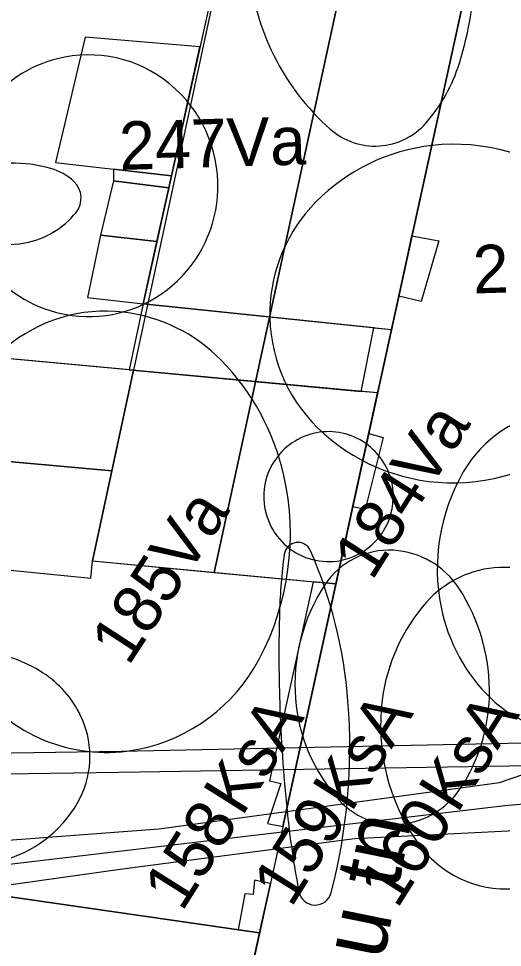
# Model space of a CAD drawing. Extents: x 738423 to 738903, y 6589762 to 6590172.
# Drawn here: x 738682.86 to 738697.88, y 6589875.99 to 6589904.84 of the extents above; entities that cross this region are included whole.
import ezdxf

# ---------------------------------------------------------------- set-up
doc = ezdxf.new("R2010")
doc.units = 0
for name, color, linetype in [('_1927_hoonestus', 7, 'Continuous'), ('_1927_katuse_kalded', 7, 'Continuous'), ('_1927_koordin_punktid_nr', 7, 'Continuous'), ('_1927_krundi_piir', 7, 'Continuous'), ('a_dendro_II_Vkl_puu', 7, 'Continuous'), ('a_dendro_III_vk_puu', 7, 'Continuous'), ('a_dendro_puu_nr', 7, 'Continuous'), ('a_dendro_V_vk_puu', 7, 'Continuous'), ('Default', 7, 'Continuous'), ('v_dp_jalak_liikumine', 7, 'Continuous'), ('v_olol_kivimuur', 7, 'Continuous'), ('v_olol_transp_jjt_jalg', 7, 'Continuous')]:
    doc.layers.add(name, color=color, linetype=linetype)

# ---------------------------------------------------------------- blocks, each defined once
blk = doc.blocks.new('_U607')
at = {"layer": 'Default'}
for centre, radius, start, end in [((-0.0026566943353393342, 0.002417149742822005), 0.005933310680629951, 70.41382597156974, 140.13835243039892), ((-0.0029635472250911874, 0.0015547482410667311), 0.006848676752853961, 31.851207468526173, 70.41382597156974), ((-0.0009113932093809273, 0.0009598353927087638), 0.008207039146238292, 140.13835243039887, 198.29664430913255), ((-0.004453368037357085, 0.0006291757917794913), 0.008602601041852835, 357.58074074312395, 31.8512074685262), ((-0.004046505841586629, 0.0006119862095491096), 0.008195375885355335, 329.5158395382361, 357.58074074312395), ((-0.0014782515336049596, 0.0007724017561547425), 0.007609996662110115, 198.29664430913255, 244.4976123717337), ((-0.0025724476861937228, -0.00025575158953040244), 0.006484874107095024, 297.8801249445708, 329.51583953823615), ((-0.0022549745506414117, -0.0008558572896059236), 0.005805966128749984, 244.49761237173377, 297.8801249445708)]:
    blk.add_arc(centre, radius, start, end, dxfattribs=at)
blk = doc.blocks.new('_U608')
at = {"layer": 'Default'}
for centre, radius, start, end in [((0.009481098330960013, -0.08696040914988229), 0.08771245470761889, 92.56418977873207, 96.25916671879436), ((0.007121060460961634, -0.034261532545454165), 0.03496075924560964, 86.71001606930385, 92.56418977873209), ((0.009078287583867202, -0.00021347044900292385), 0.0008564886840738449, 297.7295735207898, 86.7100160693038), ((0.010805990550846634, -0.09904005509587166), 0.09986454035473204, 96.25916671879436, 100.11218472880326), ((0.0033517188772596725, -0.057243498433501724), 0.057408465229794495, 100.11218472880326, 105.19470699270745), ((-0.004151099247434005, 0.024953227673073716), 0.029288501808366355, 278.76076634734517, 297.72957352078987), ((-0.011425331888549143, -0.002835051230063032), 0.0010290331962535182, 105.19470699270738, 259.83903656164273), ((-0.00521161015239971, 0.031834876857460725), 0.036251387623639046, 259.83903656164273, 278.7607663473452)]:
    blk.add_arc(centre, radius, start, end, dxfattribs=at)
blk = doc.blocks.new('_U609')
at = {"layer": 'Default'}
for centre, radius, start, end in [((0.001106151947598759, -0.004509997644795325), 0.010647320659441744, 98.77137883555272, 136.42007090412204), ((0.0011991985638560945, -0.005113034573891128), 0.011257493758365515, 60.88685880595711, 98.77137883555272), ((0.004353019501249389, 0.0005502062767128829), 0.004775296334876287, 1.0967223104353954, 60.88685880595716), ((-0.003287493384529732, -0.00032891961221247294), 0.004582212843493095, 136.42007090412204, 195.34541105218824), ((0.0039296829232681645, 0.0005421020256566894), 0.005198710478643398, 307.4116094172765, 1.0967223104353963), ((-0.002796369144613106, -0.0001941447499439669), 0.005091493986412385, 195.34541105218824, 241.43290440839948), ((-3.278635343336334e-05, 0.005722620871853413), 0.011720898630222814, 272.4097661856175, 307.4116094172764), ((6.880749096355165e-08, 0.004941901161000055), 0.010939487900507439, 241.43290440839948, 272.4097661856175)]:
    blk.add_arc(centre, radius, start, end, dxfattribs=at)
blk = doc.blocks.new('_U610')
at = {"layer": 'Default'}
for centre, radius, start, end in [((-0.0012618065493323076, -0.005464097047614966), 0.012690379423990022, 87.04508293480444, 129.22704302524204), ((-0.0011898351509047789, -0.004069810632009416), 0.011294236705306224, 52.756335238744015, 87.04508293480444), ((0.001770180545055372, -0.00017629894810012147), 0.006403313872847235, 6.66139037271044, 52.756335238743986), ((-0.005021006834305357, -0.0008593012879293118), 0.006745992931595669, 129.227043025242, 188.37609841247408), ((0.0017751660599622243, -0.0001757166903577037), 0.006398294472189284, 318.6631581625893, 6.661390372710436), ((-0.004903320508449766, -0.0008419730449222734), 0.006864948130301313, 188.37609841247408, 243.48107124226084), ((-0.002013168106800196, 0.0031567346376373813), 0.011443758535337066, 283.25261296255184, 318.6631581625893), ((-0.002300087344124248, 0.004374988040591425), 0.012695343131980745, 243.48107124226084, 283.25261296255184)]:
    blk.add_arc(centre, radius, start, end, dxfattribs=at)
blk = doc.blocks.new('_U633')
at = {"layer": 'Default'}
for centre, radius, start, end in [((0.002370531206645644, -0.00350259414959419), 0.010922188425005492, 105.74128155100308, 140.24396129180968), ((0.002663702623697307, -0.004542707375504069), 0.012002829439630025, 64.20721940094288, 105.74128155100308), ((0.004494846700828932, -0.0007535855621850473), 0.007794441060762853, 11.999792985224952, 64.20721940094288), ((-0.0004115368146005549, -0.0011882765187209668), 0.0073033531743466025, 140.24396129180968, 182.77251807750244), ((0.004826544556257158, -0.0006830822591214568), 0.007455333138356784, 311.34061200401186, 11.999792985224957), ((-0.0005976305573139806, -0.0011972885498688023), 0.007117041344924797, 182.7725180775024, 227.74554450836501), ((0.0019060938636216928, 0.0026364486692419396), 0.011876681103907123, 264.1733667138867, 311.3406120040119), ((0.0017821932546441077, 0.0014222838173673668), 0.010656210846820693, 227.74554450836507, 264.1733667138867)]:
    blk.add_arc(centre, radius, start, end, dxfattribs=at)
blk = doc.blocks.new('_U634')
at = {"layer": 'Default'}
for centre, radius, start, end in [((0.0001164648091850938, 4.298648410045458e-06), 0.004043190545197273, 50.23157481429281, 96.87125108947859), ((0.00011641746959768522, 4.691494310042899e-06), 0.00404279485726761, 96.8712510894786, 147.5024565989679), ((0.0001360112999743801, 2.7785381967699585e-05), 0.004012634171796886, 3.4041050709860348, 50.2315748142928), ((9.011818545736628e-05, 2.144440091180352e-05), 0.004011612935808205, 147.5024565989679, 198.34401257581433), ((0.00013248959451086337, 2.7575900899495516e-05), 0.0040161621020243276, 318.02683181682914, 3.4041050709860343), ((9.5093701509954e-05, 2.3094136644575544e-05), 0.004016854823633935, 198.34401257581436, 235.6502501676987), ((0.00011026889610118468, 4.7564673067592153e-05), 0.004046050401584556, 272.82677822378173, 318.0268318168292), ((0.00011037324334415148, 4.545138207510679e-05), 0.004043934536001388, 235.65025016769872, 272.82677822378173)]:
    blk.add_arc(centre, radius, start, end, dxfattribs=at)
blk = doc.blocks.new('_U635')
at = {"layer": 'Default'}
for centre, radius, start, end in [((-0.0030800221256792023, -0.004084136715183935), 0.01621807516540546, 82.51786558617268, 131.80255217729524), ((-0.002834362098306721, -0.0022136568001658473), 0.014331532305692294, 44.52272470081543, 82.51786558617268), ((-0.007166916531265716, 0.0004863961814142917), 0.010086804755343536, 131.80255217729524, 195.63791634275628), ((0.0005540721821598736, 0.0011187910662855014), 0.009578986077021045, 357.5943351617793, 44.52272470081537), ((-1.0473925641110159e-05, 0.0011425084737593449), 0.010144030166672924, 318.7914036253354, 357.5943351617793), ((-0.006344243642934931, 0.000716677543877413), 0.010941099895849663, 195.63791634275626, 246.29930243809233), ((-0.0035940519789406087, 0.0042806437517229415), 0.014907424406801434, 286.9840068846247, 318.7914036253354), ((-0.004080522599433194, 0.005873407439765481), 0.016572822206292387, 246.2993024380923, 286.9840068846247)]:
    blk.add_arc(centre, radius, start, end, dxfattribs=at)
blk = doc.blocks.new('_U694')
at = {"layer": 'Default'}
for centre, radius, start, end in [((0.0004283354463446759, -0.0021435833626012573), 0.008211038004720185, 96.61449276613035, 136.42007091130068), ((0.00042891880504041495, -0.0021486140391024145), 0.008216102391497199, 57.797497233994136, 96.61449276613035), ((0.0005495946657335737, -0.0019570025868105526), 0.007989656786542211, 18.41186471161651, 57.79749723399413), ((0.0002597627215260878, -0.001983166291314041), 0.007978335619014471, 136.4200709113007, 176.82690829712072), ((0.0006022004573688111, -0.0019394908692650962), 0.007934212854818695, 325.04588222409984, 18.411864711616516), ((0.00021332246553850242, -0.0019805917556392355), 0.007931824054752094, 176.8269082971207, 225.1076301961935), ((0.000388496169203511, -0.001790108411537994), 0.008194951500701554, 272.6016373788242, 325.04588222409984), ((0.00038913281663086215, -0.0018041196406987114), 0.008180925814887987, 225.10763019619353, 272.6016373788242)]:
    blk.add_arc(centre, radius, start, end, dxfattribs=at)
blk = doc.blocks.new('_U695')
at = {"layer": 'Default'}
for centre, radius, start, end in [((-0.0015650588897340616, 0.0029536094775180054), 0.001602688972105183, 41.6369302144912, 147.50245663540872), ((0.0024974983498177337, 0.0003657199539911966), 0.006419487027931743, 147.50245663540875, 194.49544515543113), ((-0.004182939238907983, 0.000626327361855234), 0.0051054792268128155, 20.879218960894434, 41.63693021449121), ((-0.008013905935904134, -0.0008349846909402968), 0.00920569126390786, 5.45854421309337, 20.87921896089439), ((-0.007349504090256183, -0.0007714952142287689), 0.008538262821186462, 348.2349755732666, 5.458544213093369), ((0.0013873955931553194, 7.872201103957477e-05), 0.005272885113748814, 194.4954451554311, 235.65025016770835), ((-0.002420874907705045, -0.0017979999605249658), 0.003503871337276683, 321.1995092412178, 348.2349755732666), ((-0.0007908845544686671, -0.003108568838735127), 0.0014123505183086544, 235.65025016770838, 321.1995092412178)]:
    blk.add_arc(centre, radius, start, end, dxfattribs=at)
blk = doc.blocks.new('_U696')
at = {"layer": 'Default'}
for centre, radius, start, end in [((-0.00034479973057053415, 0.00015517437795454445), 0.009857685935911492, 92.75102150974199, 139.98544812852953), ((-0.00034091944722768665, 7.442147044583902e-05), 0.009938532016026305, 49.68529801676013, 92.75102150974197), ((-0.001689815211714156, -0.0015153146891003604), 0.01202342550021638, 10.698469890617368, 49.685298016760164), ((0.0013139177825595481, -0.0012373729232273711), 0.012023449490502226, 139.9854481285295, 182.52409756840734), ((-0.001913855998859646, -0.0015576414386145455), 0.01225142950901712, 325.8315695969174, 10.698469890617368), ((0.0014915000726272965, -0.001229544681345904), 0.0122012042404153, 182.52409756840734, 226.6848242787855), ((-4.8604199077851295e-05, -0.0028237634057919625), 0.009997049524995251, 275.8525999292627, 325.83156959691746), ((-4.497698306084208e-05, -0.0028591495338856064), 0.009961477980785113, 226.68482427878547, 275.8525999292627)]:
    blk.add_arc(centre, radius, start, end, dxfattribs=at)
blk = doc.blocks.new('_U693')
at = {"layer": 'Default'}
for centre, radius, start, end in [((0.0014736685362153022, -0.0048970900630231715), 0.015073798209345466, 98.7443079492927, 142.7779679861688), ((0.0017097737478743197, -0.006432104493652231), 0.01662686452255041, 54.774629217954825, 98.74430794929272), ((0.008815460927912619, 0.003631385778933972), 0.004307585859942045, 320.0766918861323, 54.77462921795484), ((-0.0071794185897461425, 0.0016762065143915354), 0.004207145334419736, 142.77796798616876, 233.18140194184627), ((0.0036181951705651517, 0.007980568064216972), 0.01108452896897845, 292.371461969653, 320.0766918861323), ((-0.0035391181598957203, 0.006539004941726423), 0.010281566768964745, 233.18140194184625, 257.0506083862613), ((-0.001092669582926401, 0.019426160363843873), 0.023461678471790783, 273.4270301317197, 292.37146196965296), ((-0.0009858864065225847, 0.01764300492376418), 0.021675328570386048, 257.0506083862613, 273.4270301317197)]:
    blk.add_arc(centre, radius, start, end, dxfattribs=at)

msp = doc.modelspace()

# ---------------------------------------------------------------- linework, layer by layer
at = {"layer": '_1927_hoonestus'}
for points in [[(738699.2597677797, 6589917.239834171), (738691.6412212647, 6589918.198471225), (738686.7271328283, 6589895.972376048), (738694.440862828, 6589895.179011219)], [(738688.4929748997, 6589903.959162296), (738684.9273902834, 6589904.263519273), (738684.0108568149, 6589900.363607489), (738687.6066468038, 6589899.950359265)], [(738685.8087518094, 6589900.1569833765), (738685.8087518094, 6589899.793234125), (738687.5238952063, 6589899.576079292), (738687.6066468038, 6589899.950359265)], [(738685.8087518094, 6589899.793234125), (738685.410419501, 6589898.104001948), (738687.1553765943, 6589897.90929412), (738687.523895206, 6589899.576079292)], [(738685.410419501, 6589898.104001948), (738684.9964863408, 6589896.172439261), (738686.7271328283, 6589895.972376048), (738687.155376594, 6589897.909294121)], [(738695.0759745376, 6589898.086536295), (738695.9106174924, 6589897.933848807), (738695.365199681, 6589896.053327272), (738694.6665260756, 6589896.2120917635)], [(738686.7271328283, 6589895.972376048), (738686.2903381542, 6589893.9246940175), (738693.4972908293, 6589893.257957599), (738693.895924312, 6589895.23505869)], [(738694.0108549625, 6589893.210446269), (738667.804973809, 6589895.634829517), (738667.2127800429, 6589889.233630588), (738685.1046234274, 6589887.453898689), (738685.1578836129, 6589887.989329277), (738692.7143690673, 6589887.27516718)], [(738693.895924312, 6589895.2350586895), (738694.440862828, 6589895.179011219), (738694.0108549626, 6589893.210446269), (738693.4972908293, 6589893.257957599)], [(738693.735935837, 6589891.951873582), (738694.1784840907, 6589891.826844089), (738693.6257156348, 6589889.590230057), (738693.2376212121, 6589889.670602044)], [(738692.0071751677, 6589887.34200395), (738690.6496365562, 6589881.159760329), (738691.008433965, 6589881.080973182), (738690.5894531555, 6589879.838668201), (738691.0686587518, 6589879.741147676), (738692.7143690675, 6589887.275167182)], [(738686.9079452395, 6589860.693508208), (738690.3471033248, 6589876.437885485), (738655.8073303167, 6589881.431195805), (738653.971798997, 6589865.440014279)], [(738689.6761634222, 6589876.534881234), (738690.3471033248, 6589876.437885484), (738690.681707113, 6589877.969693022), (738690.187534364, 6589878.077638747), (738690.1417332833, 6589877.62666165), (738689.8836035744, 6589877.652877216)]]:
    msp.add_lwpolyline(points, close=True, dxfattribs=at)
at = {"layer": '_1927_katuse_kalded'}
for points in [[(738695.4504945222, 6589917.719152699), (738691.6412212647, 6589918.198471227), (738685.1578836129, 6589887.989329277), (738688.93612634, 6589887.632248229)], [(738688.9361263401, 6589887.632248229), (738692.7143690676, 6589887.275167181), (738699.2597677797, 6589917.239834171), (738695.4504945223, 6589917.719152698)], [(738685.7580226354, 6589890.785679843), (738686.4289503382, 6589893.911870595), (738667.804973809, 6589895.634829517), (738667.5088769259, 6589892.434230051)], [(738685.1046234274, 6589887.453898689), (738685.1578836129, 6589887.989329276), (738685.7580226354, 6589890.785679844), (738667.508876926, 6589892.434230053), (738667.2127800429, 6589889.233630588)], [(738654.1081769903, 6589873.783129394), (738655.0056644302, 6589881.575610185), (738655.8073303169, 6589881.431195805), (738690.3471033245, 6589876.437885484), (738688.7887442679, 6589869.303757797)]]:
    msp.add_lwpolyline(points, close=True, dxfattribs=at)
at = {"layer": '_1927_krundi_piir'}
msp.add_lwpolyline([(738699.2597677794, 6589917.23983417), (738686.9079452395, 6589860.693508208), (738653.160733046, 6589865.556898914), (738635.0048101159, 6589867.503013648), (738638.1290908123, 6589898.927727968), (738639.279366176, 6589910.5516114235)], dxfattribs=at)
at = {"layer": 'v_dp_jalak_liikumine'}
msp.add_lwpolyline([(738581.4723412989, 6589878.120522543), (738587.4015406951, 6589878.120522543), (738606.5184403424, 6589878.608756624), (738618.5434188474, 6589878.425595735), (738641.8496480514, 6589878.136204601), (738655.9728153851, 6589879.813491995), (738670.3230528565, 6589879.497843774), (738680.5529887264, 6589878.338003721), (738697.9581193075, 6589880.397873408), (738705.6932562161, 6589881.082962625), (738725.5888177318, 6589880.833839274), (738742.0007790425, 6589880.833839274), (738745.4047050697, 6589880.7783847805), (738754.5304628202, 6589882.343075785), (738758.8441211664, 6589885.746853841)], dxfattribs=at)
at = {"layer": 'v_olol_kivimuur'}
msp.add_lwpolyline([(738659.9889999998, 6589880.999), (738668.9849999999, 6589881.181999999), (738685.9700000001, 6589881.434000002), (738699.3649999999, 6589881.647999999), (738707.9990000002, 6589881.8900000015), (738716.541, 6589882.000000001), (738723.847358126, 6589882.143855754), (738735.8410000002, 6589882.379999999), (738754.0880000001, 6589882.902), (738754.024, 6589883.413000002), (738735.8970000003, 6589882.9909999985), (738716.5100000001, 6589882.6219999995), (738707.99, 6589882.534999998), (738699.5579999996, 6589882.3539999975), (738686.0599999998, 6589882.071000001), (738669.01, 6589881.818000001), (738666.875, 6589881.770000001), (738659.944, 6589881.638000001)], dxfattribs=at)
at = {"layer": 'v_olol_transp_jjt_jalg'}
for points in [[(738659.9889999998, 6589880.999), (738668.9849999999, 6589881.181999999), (738670.3032881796, 6589881.201558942), (738670.34, 6589878.036999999), (738670.34, 6589878.036999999), (738670.3128629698, 6589880.376211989), (738673.4449999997, 6589879.948), (738680.7409005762, 6589879.183086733), (738687.2215764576, 6589879.67051432), (738697.799, 6589881.108999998), (738699.3649999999, 6589881.647999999)], [(738699.0990000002, 6589879.646000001), (738693.2890000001, 6589879.360999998), (738686.0879999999, 6589878.418), (738682.2479999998, 6589877.876000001), (738679.7519999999, 6589877.738000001), (738672.9870000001, 6589877.782), (738670.507, 6589877.988999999), (738669.2659999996, 6589877.994000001), (738669.256, 6589877.913000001), (738666.5159999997, 6589877.835999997), (738664.931, 6589878.489), (738662.7329999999, 6589878.602000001), (738660.8409999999, 6589878.633999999)]]:
    msp.add_lwpolyline(points, dxfattribs=at)

# ---------------------------------------------------------------- block references
at = {"layer": 'a_dendro_II_Vkl_puu', "xscale": 500.0000000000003, "yscale": 500.0000000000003, "rotation": 85.69234851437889}
for name, p in [('_U633', (738699.498, 6589886.586999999)), ('_U634', (738692.4939999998, 6589889.931000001)), ('_U608', (738691.087, 6589883.62)), ('_U609', (738694.4769999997, 6589883.745999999)), ('_U610', (738697.7709999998, 6589883.711999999)), ('_U607', (738681.8327824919, 6589883.078))]:
    msp.add_blockref(name, p, dxfattribs=at)
at = {"layer": 'a_dendro_III_vk_puu', "xscale": 500.0000000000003, "yscale": 500.0000000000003, "rotation": 85.69234851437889}
for name, p in [('_U694', (738684.0480000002, 6589899.514000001)), ('_U696', (738695.681, 6589895.819)), ('_U635', (738686.0960000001, 6589890.641000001))]:
    msp.add_blockref(name, p, dxfattribs=at)
at = {"layer": 'a_dendro_V_vk_puu', "xscale": 500.0000000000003, "yscale": 500.0000000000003, "rotation": 85.69234851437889}
for name, p in [('_U693', (738695.034, 6589906.495999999)), ('_U695', (738682.577, 6589899.7700000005))]:
    msp.add_blockref(name, p, dxfattribs=at)

# ---------------------------------------------------------------- texts
at = {"layer": '_1927_koordin_punktid_nr'}
msp.add_text('Rahu tn', height=1.999999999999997, rotation=78.4840469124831, dxfattribs=at).set_placement((738693.2020124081, 6589870.754290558))
at = {"layer": 'a_dendro_puu_nr'}
for s, height, rotation, p in [('247Va', 1.5, 1.7381147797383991, (738686.0040610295, 6589900.13207225)), ('249Hks', 1.5, 1.7381147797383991, (738696.9866738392, 6589896.295761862)), ('184Va', 1.5000000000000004, 57.784522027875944, (738693.8321686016, 6589887.3436216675)), ('185Va', 1.5000000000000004, 56.88665020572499, (738686.2724087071, 6589884.696461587)), ('KsA', 1.5000000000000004, 57.784522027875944, (738689.7970811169, 6589880.021746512)), ('KsA', 1.5000000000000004, 57.784522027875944, (738693.1870811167, 6589880.147746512)), ('KsA', 1.5000000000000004, 57.784522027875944, (738696.4810811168, 6589880.113746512)), ('158', 1.5000000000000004, 57.784522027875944, (738687.9332141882, 6589877.063748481)), ('159', 1.5000000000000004, 57.784522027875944, (738691.3232141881, 6589877.189748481)), ('160', 1.5000000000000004, 57.784522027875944, (738694.6172141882, 6589877.155748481))]:
    msp.add_text(s, height=height, rotation=rotation, dxfattribs=at).set_placement(p)

doc.saveas('drawing.dxf')
